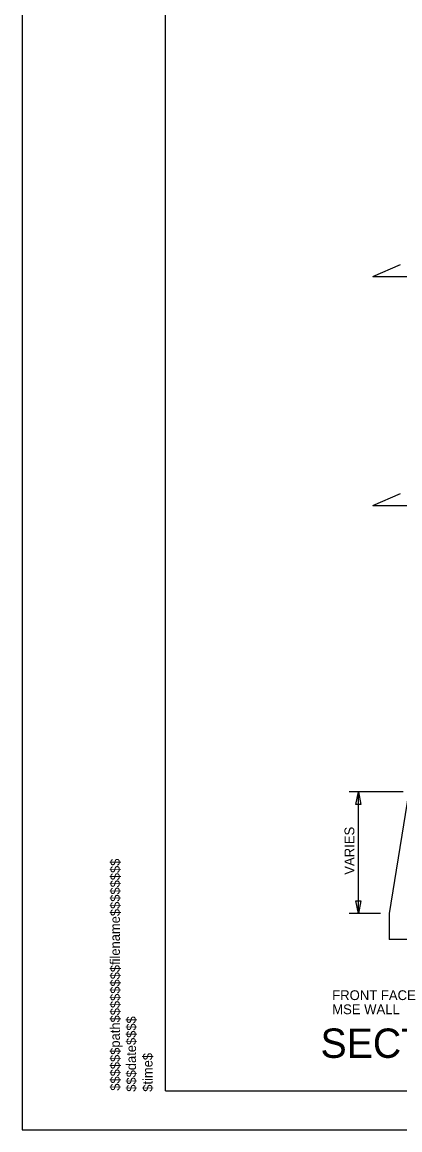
# Model space of a CAD drawing. Extents: x 96 to 240, y 601 to 689.
# Drawn here: x 95.8 to 115.2, y 601 to 657.6 of the extents above; entities that cross this region are included whole.
import ezdxf

# ---------------------------------------------------------------- set-up
doc = ezdxf.new("R2010")
doc.units = 0
for name, color, linetype in [('BR_AUTO DIMENSION', 7, 'Continuous'), ('BR_BORDER LINES', 7, 'Continuous'), ('BR_CONCRETE', 7, 'Continuous'), ('BR_TEXT', 7, 'Continuous'), ('Level 31', 7, 'Continuous'), ('RD_SHT_ID', 7, 'Continuous')]:
    doc.layers.add(name, color=color, linetype=linetype)

msp = doc.modelspace()

# ---------------------------------------------------------------- linework, layer by layer
at = {"layer": 'BR_AUTO DIMENSION'}
for p, q in [((113.78, 644.618), (115.181, 645.233)), ((113.78, 644.618), (116.921, 644.618)), ((113.78, 632.914), (115.181, 633.529)), ((113.78, 632.914), (116.921, 632.914)), ((115.328, 618.281), (112.555, 618.281)), ((113.036, 612.058), (113.036, 618.281)), ((114.157, 612.058), (112.555, 612.058))]:
    msp.add_line(p, q, dxfattribs=at)
for points in [[(112.911, 617.631), (113.036, 618.281), (113.161, 617.631)], [(113.161, 612.708), (113.036, 612.058), (112.911, 612.708)]]:
    msp.add_lwpolyline(points, close=True, dxfattribs=at)
at = {"layer": 'BR_BORDER LINES'}
for q in [(103.173, 687.003), (237.837, 603.003)]:
    msp.add_line((103.173, 603.003), q, dxfattribs=at)
at = {"layer": 'BR_CONCRETE'}
for p, q in [((115.608, 618.281), (114.608, 612.058)), ((114.608, 612.058), (114.608, 610.725)), ((117.274, 610.725), (114.608, 610.725))]:
    msp.add_line(p, q, dxfattribs=at)
at = {"layer": 'Level 31'}
msp.add_lwpolyline([(95.84, 689.004), (95.84, 601.004), (239.84, 601.004), (239.84, 689.004)], dxfattribs=at)

# ---------------------------------------------------------------- texts
at = {"layer": 'BR_AUTO DIMENSION'}
msp.add_text('VARIES', height=0.5, rotation=90, dxfattribs=at).set_placement((112.825, 614.042))
for s, p in [('FRONT FACE', (111.695, 607.637)), ('MSE WALL', (111.695, 606.916))]:
    msp.add_text(s, height=0.5, dxfattribs=at).set_placement(p)
at = {"layer": 'BR_TEXT'}
msp.add_text('SECTION A-A', height=1.5, dxfattribs=at).set_placement((111.098, 604.683))
at = {"layer": 'RD_SHT_ID'}
for s, height, p in [('$$$$$$path$$$$$$$$filename$$$$$$$$', 0.49387, (100.839, 603.003)), ('$$$date$$$$', 0.49387, (101.662, 602.951)), ('$time$', 0.4939, (102.507, 602.951))]:
    msp.add_text(s, height=height, rotation=90, dxfattribs=at).set_placement(p)

doc.saveas('drawing.dxf')
